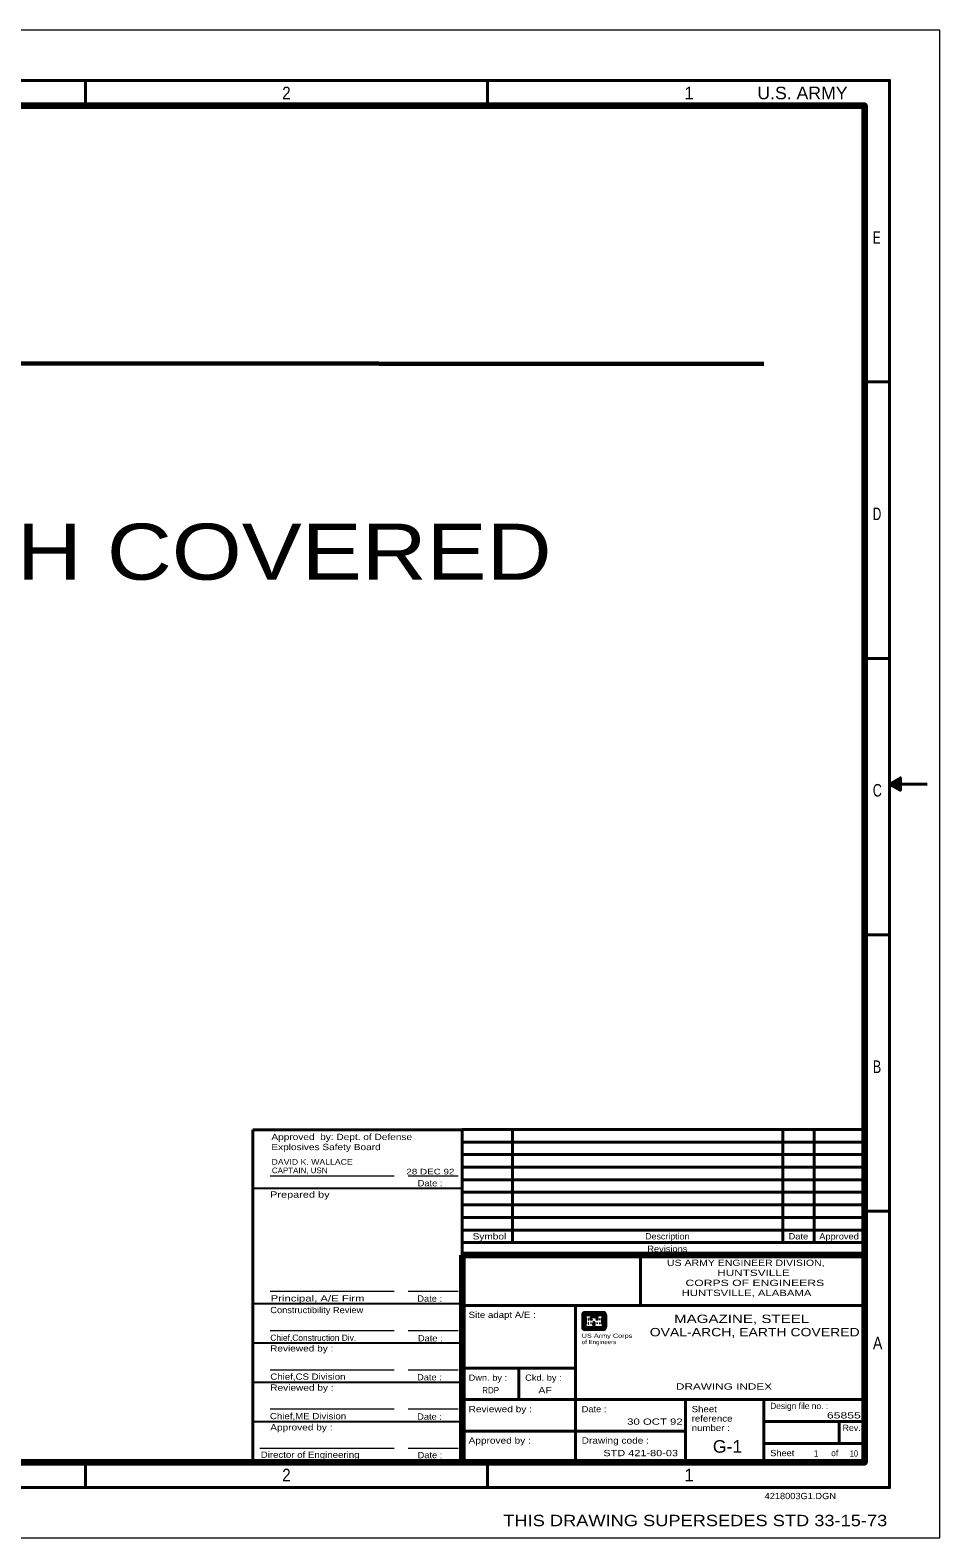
# Model space of a CAD drawing. Extents: x -7.4 to 34.6, y -51.3 to -21.3.
# Drawn here: x 16.55 to 34.65, y -51.27 to -21.27 of the extents above; entities that cross this region are included whole.
import ezdxf
from ezdxf.enums import TextEntityAlignment as Align

# ---------------------------------------------------------------- set-up
doc = ezdxf.new("R2010")
doc.units = 0
doc.header["$LTSCALE"] = 0.05
doc.layers.add('1', color=7, linetype='Continuous')
doc.layers.add('4', color=7, linetype='Continuous', lineweight=40)

msp = doc.modelspace()

# ---------------------------------------------------------------- linework, layer by layer
at = {"layer": '4', "lineweight": 13}
for p, q in [((34.64802, -21.26987), (-7.35198, -21.26987)), ((23.79407, -44.07088), (21.32332, -44.07088)), ((25.06202, -44.07088), (24.0737, -44.07088)), ((23.79407, -46.36795), (21.32332, -46.36795)), ((25.06202, -46.36795), (24.0737, -46.36795)), ((27.95177, -46.76987), (27.5874, -46.76987)), ((27.95177, -46.77362), (27.5874, -46.77362)), ((27.95177, -46.77862), (27.5874, -46.77862)), ((27.95177, -46.78388), (27.5874, -46.78388)), ((27.95177, -46.78925), (27.5874, -46.78925)), ((27.52302, -46.83425), (27.52302, -47.0805)), ((27.52677, -46.83425), (27.52677, -47.0805)), ((27.53215, -46.83425), (27.53215, -47.0805)), ((27.53715, -46.83425), (27.53715, -47.0805)), ((27.5424, -46.83425), (27.5424, -47.0805)), ((27.5634, -46.83425), (27.5634, -47.0805)), ((27.5684, -46.83425), (27.5684, -47.0805)), ((27.57365, -46.83425), (27.57365, -47.0805)), ((27.57902, -46.83425), (27.57902, -47.0805)), ((27.58402, -46.83425), (27.58402, -47.0805)), ((27.95177, -46.80987), (27.5874, -46.80987)), ((27.95177, -46.81513), (27.5874, -46.81513)), ((27.95177, -46.8205), (27.5874, -46.8205)), ((27.95177, -46.8255), (27.5874, -46.8255)), ((27.95177, -46.83075), (27.5874, -46.83075)), ((27.95177, -47.08387), (27.5874, -47.08387)), ((27.95177, -47.08888), (27.5874, -47.08888)), ((27.95177, -47.09425), (27.5874, -47.09425)), ((27.95177, -47.0995), (27.5874, -47.0995)), ((27.58927, -46.83425), (27.58927, -47.07862)), ((27.94965, -47.07862), (27.58927, -47.07862)), ((27.59465, -46.83425), (27.59465, -47.07325)), ((27.94465, -47.07325), (27.59465, -47.07325)), ((27.59865, -46.88675), (27.59865, -47.01237)), ((27.60402, -46.892), (27.60402, -47.00675)), ((27.71365, -46.8355), (27.82552, -46.8355)), ((27.71365, -46.84075), (27.82552, -46.84075)), ((27.71365, -46.84575), (27.82552, -46.84575)), ((27.71365, -46.85112), (27.82552, -46.85112)), ((27.71365, -46.85637), (27.82552, -46.85637)), ((27.71365, -46.86137), (27.82552, -46.86137)), ((27.71365, -46.86675), (27.82552, -46.86675)), ((27.74527, -47.03762), (27.74527, -46.99737)), ((27.74527, -47.03762), (27.79365, -47.03762)), ((27.75052, -47.03762), (27.75052, -46.99737)), ((27.75552, -47.03762), (27.75552, -46.99737)), ((27.7609, -47.03762), (27.7609, -46.99737)), ((27.76615, -47.03762), (27.76615, -46.99737)), ((27.77302, -47.03762), (27.77302, -46.99737)), ((27.77802, -47.03762), (27.77802, -46.99737)), ((27.7834, -47.03762), (27.7834, -46.99737)), ((27.78865, -47.03762), (27.78865, -46.99737)), ((27.79365, -47.03762), (27.79365, -46.99737)), ((27.93527, -46.892), (27.93527, -47.00675)), ((27.94027, -46.887), (27.94027, -47.01175)), ((27.94465, -46.83425), (27.94465, -47.07325)), ((27.94965, -46.83425), (27.94965, -47.07862)), ((27.9549, -46.83425), (27.9549, -47.0805)), ((27.96027, -46.83425), (27.96027, -47.0805)), ((27.96527, -46.83425), (27.96527, -47.0805)), ((27.97052, -46.83425), (27.97052, -47.0805)), ((27.9759, -46.83425), (27.9759, -47.0805)), ((27.99652, -46.83425), (27.99652, -47.0805)), ((28.00177, -46.83425), (28.00177, -47.0805)), ((28.00715, -46.83425), (28.00715, -47.0805)), ((28.01215, -46.83425), (28.01215, -47.0805)), ((28.0159, -46.83425), (28.0159, -47.0805)), ((23.79407, -47.1492), (21.32332, -47.1492)), ((25.06202, -47.1492), (24.0737, -47.1492)), ((27.95177, -47.1045), (27.5874, -47.1045)), ((27.95177, -47.1255), (27.5874, -47.1255)), ((27.95177, -47.13075), (27.5874, -47.13075)), ((27.95177, -47.13575), (27.5874, -47.13575)), ((27.95177, -47.14112), (27.5874, -47.14112)), ((27.95177, -47.14487), (27.5874, -47.14487)), ((23.79407, -47.93045), (21.32332, -47.93045)), ((25.06202, -47.93045), (24.0737, -47.93045)), ((23.79407, -48.7117), (21.32332, -48.7117)), ((25.06202, -48.7117), (24.0737, -48.7117)), ((23.79407, -49.49295), (21.11913, -49.49295)), ((25.06202, -49.49295), (24.0737, -49.49295))]:
    msp.add_line(p, q, dxfattribs=at)
at = {"layer": '4'}
for p, q in [((17.64807, -22.26998), (17.64807, -22.76998)), ((25.64805, -22.26998), (25.64805, -22.76998)), ((0.18009, -27.87243), (31.14682, -27.89909)), ((0.18009, -27.87965), (31.1468, -27.9063)), ((0.18007, -27.9003), (31.1468, -27.92698)), ((33.14802, -28.26995), (33.64802, -28.26995)), ((33.14802, -33.76995), (33.64802, -33.76995)), ((33.64802, -36.26993), (34.39802, -36.26993)), ((33.14802, -39.26991), (33.64802, -39.26991)), ((20.97695, -43.15397), (20.97695, -49.77897)), ((25.14802, -43.15397), (20.97695, -43.15397)), ((25.14802, -43.14487), (25.14802, -45.64487)), ((33.14802, -43.14487), (25.14802, -43.14487)), ((26.14802, -43.14487), (26.14802, -45.39487)), ((31.52302, -43.14487), (31.52302, -45.39487)), ((32.14802, -43.14487), (32.14802, -45.39487)), ((33.14802, -43.39487), (25.14802, -43.39487)), ((33.14802, -43.64487), (25.14802, -43.64487)), ((33.14802, -43.89487), (25.14802, -43.89487)), ((33.14802, -44.14487), (25.14802, -44.14487)), ((33.14802, -44.39487), (25.14802, -44.39487)), ((33.14802, -44.64487), (25.14802, -44.64487)), ((33.14802, -44.89487), (25.14802, -44.89487)), ((33.14802, -44.76991), (33.64802, -44.76991)), ((33.14802, -45.14487), (25.14802, -45.14487)), ((33.14802, -45.39487), (25.14802, -45.39487)), ((28.69552, -45.64487), (28.69552, -46.64487)), ((33.14802, -46.64487), (25.14802, -46.64487)), ((27.39802, -46.64487), (27.39802, -49.76987)), ((27.39802, -47.89487), (25.14802, -47.89487)), ((26.27302, -47.89487), (26.27302, -48.51987)), ((33.14802, -48.51987), (25.14802, -48.51987)), ((29.58552, -48.51987), (29.58552, -49.76987)), ((31.14802, -48.51987), (31.14802, -49.76987)), ((29.58552, -49.14487), (25.14802, -49.14487)), ((33.14802, -48.95737), (31.14802, -48.95737)), ((32.64802, -48.95737), (32.64802, -49.39487)), ((33.14802, -49.39487), (31.14802, -49.39487)), ((17.64807, -49.76987), (17.64807, -50.26987)), ((25.64805, -49.76987), (25.64805, -50.26987))]:
    msp.add_line(p, q, dxfattribs=at)
at = {"layer": '4', "lineweight": 25}
for p, q in [((25.1669, -44.31968), (20.97695, -44.31968)), ((25.1669, -46.61675), (20.97695, -46.61675)), ((25.1669, -47.398), (20.97695, -47.398)), ((25.1669, -48.17925), (20.97695, -48.17925)), ((25.16657, -48.9605), (20.97662, -48.9605))]:
    msp.add_line(p, q, dxfattribs=at)
at = {"layer": '4', "lineweight": 90}
for p, q in [((25.14802, -45.64487), (25.14802, -49.76987)), ((33.14802, -45.64487), (25.14802, -45.64487))]:
    msp.add_line(p, q, dxfattribs=at)
at = {"layer": '4', "lineweight": 13}
for points in [[(-7.35198, -51.26991), (34.64802, -51.26991), (34.64802, -21.26987)], [(27.70802, -46.89112), (27.7049, -46.89425), (27.7049, -46.92825), (27.7159, -46.92825), (27.7084, -46.92075), (27.7084, -46.89075)], [(27.83115, -46.89112), (27.83427, -46.89425), (27.83427, -46.92825), (27.8234, -46.92825), (27.83052, -46.92075), (27.83052, -46.89075)]]:
    msp.add_lwpolyline(points, dxfattribs=at)
at = {"layer": '4'}
for points in [[(-6.3518, -50.26987), (-6.3518, -22.26998), (33.64802, -22.26998), (33.64802, -50.26987)], [(33.64802, -36.26993), (33.86452, -36.14493), (33.86452, -36.39493)]]:
    msp.add_lwpolyline(points, close=True, dxfattribs=at)
at = {"layer": '4', "lineweight": 90}
msp.add_lwpolyline([(-4.85183, -22.76998), (33.14802, -22.76998), (33.14802, -49.76987), (-4.85183, -49.76987)], close=True, dxfattribs=at)
at = {"layer": '4'}
for points in [[(33.69072, -36.26935), (33.8437, -36.181), (33.8437, -36.35882), (33.69145, -36.27095)], [(33.7302, -36.2706), (33.82282, -36.21709), (33.82282, -36.32275), (33.72925, -36.26873)], [(33.77257, -36.27018), (33.80202, -36.25318), (33.80202, -36.28668), (33.77584, -36.27157)]]:
    msp.add_lwpolyline(points, dxfattribs=at)
at = {"layer": '4', "lineweight": 13}
for points in [[(27.5984, -46.8345), (27.5984, -46.88137), (27.60902, -46.892), (27.60902, -47.00675), (27.5984, -47.01738), (27.5984, -47.0695), (27.94052, -47.0695), (27.94052, -47.01738), (27.9299, -47.00675), (27.9299, -46.892), (27.94052, -46.88137), (27.94052, -46.8345), (27.89552, -46.8345), (27.86052, -46.8345), (27.82865, -46.8345), (27.82865, -46.88137), (27.83965, -46.892), (27.83965, -46.93362), (27.81465, -46.93362), (27.81465, -46.9295), (27.82552, -46.91887), (27.82552, -46.872), (27.78027, -46.872), (27.74552, -46.872), (27.71365, -46.872), (27.71365, -46.91887), (27.72427, -46.9295), (27.72427, -46.93362), (27.69965, -46.93362), (27.69965, -46.892), (27.71027, -46.88137), (27.71027, -46.8345), (27.6649, -46.8345), (27.63027, -46.8345)], [(27.60365, -46.8395), (27.60365, -46.87925), (27.61427, -46.88987), (27.61427, -47.00862), (27.60365, -47.0195), (27.60365, -47.06425), (27.93552, -47.06425), (27.93552, -47.0195), (27.92465, -47.00862), (27.92465, -46.88987), (27.93552, -46.87925), (27.93552, -46.8395), (27.90365, -46.8395), (27.90365, -46.85825), (27.90052, -46.85825), (27.90052, -46.8395), (27.86865, -46.8395), (27.86865, -46.85825), (27.8659, -46.85825), (27.8659, -46.8395), (27.83402, -46.8395), (27.83402, -46.87925), (27.84465, -46.88987), (27.84465, -46.93863), (27.80965, -46.93863), (27.80965, -46.92737), (27.82027, -46.91675), (27.82027, -46.877), (27.7884, -46.877), (27.7884, -46.89575), (27.78552, -46.89575), (27.78552, -46.877), (27.75365, -46.877), (27.75365, -46.89575), (27.75052, -46.89575), (27.75052, -46.877), (27.71865, -46.877), (27.71865, -46.91675), (27.72965, -46.92737), (27.72965, -46.93863), (27.69427, -46.93863), (27.69427, -46.88987), (27.70527, -46.87925), (27.70527, -46.8395), (27.6734, -46.8395), (27.6734, -46.85825), (27.67027, -46.85825), (27.67027, -46.8395), (27.6384, -46.8395), (27.6384, -46.85825), (27.63552, -46.85825), (27.63552, -46.8395)], [(27.65277, -46.90362), (27.65277, -46.93863), (27.6559, -46.93863), (27.6559, -46.90362)], [(27.65277, -46.98387), (27.65277, -47.01888), (27.6559, -47.01888), (27.6559, -46.98387)], [(27.70777, -46.98387), (27.70777, -47.00825), (27.7109, -47.00825), (27.7109, -46.98387)], [(27.83115, -46.98387), (27.83115, -47.00825), (27.8284, -47.00825), (27.8284, -46.98387)], [(27.88615, -46.90362), (27.88615, -46.93863), (27.88302, -46.93863), (27.88302, -46.90362)], [(27.88615, -46.98387), (27.88615, -47.01888), (27.88302, -47.01888), (27.88302, -46.98387)]]:
    msp.add_lwpolyline(points, close=True, dxfattribs=at)
for centre, radius, start, end in [((27.58731, -46.83416), 0.06429, 89.99998, 179.99997), ((27.58731, -46.83416), 0.06057, 89.99998, 179.99997), ((27.58731, -46.83416), 0.05536, 89.99998, 179.99997), ((27.58731, -46.83416), 0.05015, 89.99998, 179.99997), ((27.58731, -46.83416), 0.04494, 89.99998, 179.99997), ((27.9516, -46.83416), 0.06429, 359.99998, 89.99998), ((27.9516, -46.83416), 0.06057, 0.00002, 90.00002), ((27.9516, -46.83416), 0.05536, 0.00002, 90.00002), ((27.9516, -46.83416), 0.05015, 0.00003, 90.00002), ((27.9516, -46.83416), 0.04494, 0.00002, 90.00002), ((27.58731, -47.08059), 0.06429, 180.00003, 270.00003), ((27.58731, -47.08059), 0.06057, 179.99998, 269.99997), ((27.58731, -47.08059), 0.05536, 179.99998, 269.99997), ((27.58731, -47.08059), 0.05015, 179.99998, 269.99997), ((27.58731, -47.08059), 0.04494, 179.99998, 269.99997), ((27.58731, -46.83416), 0.02411, 89.99998, 179.99997), ((27.58731, -47.08059), 0.02411, 180.00003, 270.00003), ((27.58731, -46.83416), 0.0189, 89.99998, 179.99997), ((27.58731, -47.08059), 0.0189, 180.00003, 270.00003), ((27.58731, -46.83416), 0.01369, 89.99998, 179.99997), ((27.58731, -47.08059), 0.01369, 180.00003, 270.00003), ((27.58731, -46.83416), 0.00848, 89.99998, 179.99997), ((27.58731, -47.08059), 0.00848, 180.00003, 270.00003), ((27.58731, -46.83416), 0.00327, 89.99998, 179.99997), ((27.58731, -47.08059), 0.00327, 180.00003, 270.00003), ((27.77843, -47.00021), 0.03332, 105.66805, 176.05748), ((27.77843, -47.00021), 0.02811, 103.46979, 176.05748), ((27.77843, -47.00021), 0.0229, 103.46979, 176.05748), ((27.77843, -47.00021), 0.0177, 103.46979, 176.05748), ((27.76048, -47.00021), 0.01249, 3.94252, 76.53021), ((27.76048, -47.00021), 0.0177, 3.94252, 76.53021), ((27.76048, -47.00021), 0.0229, 3.94252, 76.53021), ((27.77843, -47.00021), 0.01249, 103.46979, 176.05748), ((27.76048, -47.00021), 0.02811, 3.94252, 76.53021), ((27.76048, -47.00021), 0.03332, 3.94252, 74.39486), ((27.9516, -46.83416), 0.02411, 359.99998, 89.99998), ((27.9516, -46.83416), 0.0189, 359.99998, 89.99998), ((27.9516, -46.83416), 0.01369, 359.99998, 89.99998), ((27.9516, -46.83416), 0.00848, 359.99998, 89.99998), ((27.9516, -46.83416), 0.00327, 359.99998, 89.99998), ((27.9516, -47.08059), 0.06429, 270.00003, 0.00003), ((27.9516, -47.08059), 0.02411, 270.00003, 0.00003), ((27.9516, -47.08059), 0.0189, 270.00003, 0.00003), ((27.9516, -47.08059), 0.01369, 270.00003, 0.00003), ((27.9516, -47.08059), 0.00848, 270.00003, 0.00003), ((27.9516, -47.08059), 0.00327, 270.00003, 0.00003), ((27.9516, -47.08059), 0.04494, 270.00002, 0.00002), ((27.9516, -47.08059), 0.05015, 270.00002, 0.00002), ((27.9516, -47.08059), 0.05536, 270.00002, 0.00002), ((27.9516, -47.08059), 0.06057, 270.00002, 0.00002)]:
    msp.add_arc(centre, radius, start, end, dxfattribs=at)

# ---------------------------------------------------------------- texts
at = {"layer": '1'}
for s, width, p in [('DAVID K. WALLACE', 1.15, (21.35288, -43.84628)), ('CAPTAIN, USN', 1.05, (21.35957, -44.01412)), ('28 DEC 92', 1.3, (24.03457, -44.03912))]:
    msp.add_text(s, height=0.1125, dxfattribs=dict(at, width=width)).set_placement(p)
at = {"layer": '1', "width": 1.2}
msp.add_text('THIS DRAWING SUPERSEDES STD 33-15-73', height=0.226, dxfattribs=at).set_placement((29.78234, -51.03787), align=Align.CENTER)
at = {"layer": '4'}
for s, height, width, p in [('2', 0.25, 0.9, (21.6484, -22.64498)), ('E', 0.25, 0.7, (33.39244, -25.51998)), ('D', 0.25, 0.7, (33.39834, -31.01998)), ('C', 0.25, 0.75, (33.40425, -36.51993)), ('B', 0.25, 0.75, (33.39834, -42.01991)), ('Symbol', 0.125, 1.2, (25.68699, -45.33237)), ('Description', 0.125, 1.05, (29.22614, -45.33237)), ('Date', 0.125, 1.1, (31.83391, -45.33237)), ('Approved', 0.125, 1.1, (32.64246, -45.33237)), ('Revisions', 0.125, 1.1, (29.22714, -45.58237)), ('    US ARMY ENGINEER DIVISION,    ', 0.125, 1.25, (30.78767, -45.85918)), ('        CORPS OF ENGINEERS        ', 0.125, 1.45, (30.96729, -46.25918)), ('            HUNTSVILLE            ', 0.125, 1.4, (30.94072, -46.05918)), ('       HUNTSVILLE, ALABAMA        ', 0.125, 1.35, (30.83336, -46.45918)), ('  OVAL-ARCH, EARTH COVERED   ', 0.1665, 1.25, (31.00349, -47.25975)), ('       MAGAZINE, STEEL       ', 0.1665, 1.35, (30.70471, -46.99498)), ('A', 0.25, 0.85, (33.41116, -47.51987)), ('RDP', 0.125, 0.95, (25.71081, -48.39487)), ('AF ', 0.125, 1.25, (26.82381, -48.39487)), ('             DRAWING INDEX              ', 0.125, 1.4, (30.38684, -48.32095)), ('2', 0.25, 0.9, (21.6484, -50.14487))]:
    msp.add_text(s, height=height, dxfattribs=dict(at, width=width)).set_placement(p, align=Align.CENTER)
for p in [(29.65847, -22.64498), (29.65847, -50.14487)]:
    msp.add_text('1', height=0.25, dxfattribs=at).set_placement(p, align=Align.CENTER)
for s, height, width, p in [('U.S. ARMY', 0.25, 1.05, (32.81199, -22.64498)), ('30 OCT 92', 0.125, 1.35, (29.53083, -49.01987)), ('         65855', 0.125, 1.45, (33.07565, -48.89487)), ('STD 421-80-03', 0.125, 1.3, (29.43932, -49.64487)), ('10', 0.125, 0.8, (33.01989, -49.65334))]:
    msp.add_text(s, height=height, dxfattribs=dict(at, width=width)).set_placement(p, align=Align.RIGHT)
for s, height, width, p in [('OVAL-ARCH, EARTH COVERED   ', 1.115, 1.2, (0.08188, -32.2047)), ('Approved  by: Dept. of Defense ', 0.125, 1.2, (21.3497, -43.3548)), ('Explosives Safety Board  ', 0.125, 1.2, (21.34937, -43.55507)), ('Prepared by              ', 0.125, 1.3, (21.32416, -44.50105)), ('Date :', 0.125, 1.1, (24.26041, -44.27625)), ('Principal, A/E Firm        ', 0.125, 1.35, (21.33407, -46.5665)), ('Date :', 0.125, 1.1, (24.2539, -46.57082)), ('Constructibility Review', 0.125, 1.1, (21.32807, -46.799)), ('Site adapt A/E :', 0.125, 1.15, (25.27302, -46.89487)), ('Date :', 0.125, 1.1, (24.26495, -47.36088)), ('of Engineers', 0.08337, 1.1, (27.52302, -47.41575)), ('US Army Corps', 0.08337, 1.3, (27.52302, -47.29075)), ('Reviewed by :', 0.125, 1.2, (21.3234, -47.5617)), ('Chief,CS Division           ', 0.125, 1.15, (21.32807, -48.12445)), ('Reviewed by :', 0.125, 1.2, (21.3272, -48.34313)), ('Date :', 0.125, 1.1, (24.24853, -48.13687)), ('Dwn. by :', 0.125, 1.1, (25.27302, -48.14487)), ('Ckd. by :', 0.125, 1.1, (26.39802, -48.14487)), ('Chief,ME Division           ', 0.125, 1.15, (21.32041, -48.90975)), ('Date :', 0.125, 1.1, (24.25045, -48.91932)), ('Reviewed by :', 0.125, 1.2, (25.27302, -48.76987)), ('Date :', 0.125, 1.1, (27.52302, -48.76987)), ('Sheet', 0.125, 1.15, (29.71052, -48.76987)), ('reference', 0.125, 1.15, (29.71052, -48.95737)), ('Approved by :', 0.125, 1.2, (21.3272, -49.13282)), ('number :', 0.125, 1.15, (29.71052, -49.14487)), ('Rev.', 0.125, 1.05, (32.71277, -49.14487)), ('Approved by :', 0.125, 1.2, (25.27302, -49.39487)), ('Drawing code :', 0.125, 1.2, (27.52302, -49.39487)), (' G-1  ', 0.2501, 1.05, (30.0341, -49.5758)), ('Director of Engineering     ', 0.125, 1.15, (21.1369, -49.67873)), ('Date :', 0.125, 1.1, (24.25857, -49.68625)), ('Sheet     ', 0.125, 1.1, (31.27302, -49.64487)), ('4218003G1.DGN', 0.125, 1.1, (31.16102, -50.49995))]:
    msp.add_text(s, height=height, dxfattribs=dict(at, width=width)).set_placement(p)
for s, p in [('Chief,Construction Div.        ', (21.32807, -47.3507)), ('Design file no. :', (31.27302, -48.70737))]:
    msp.add_text(s, height=0.125, dxfattribs=at).set_placement(p)
for s, p in [(' 1', (32.23391, -49.65334)), ('of', (32.62553, -49.64487))]:
    msp.add_text(s, height=0.125, dxfattribs=at).set_placement(p, align=Align.RIGHT)

doc.saveas('drawing.dxf')
